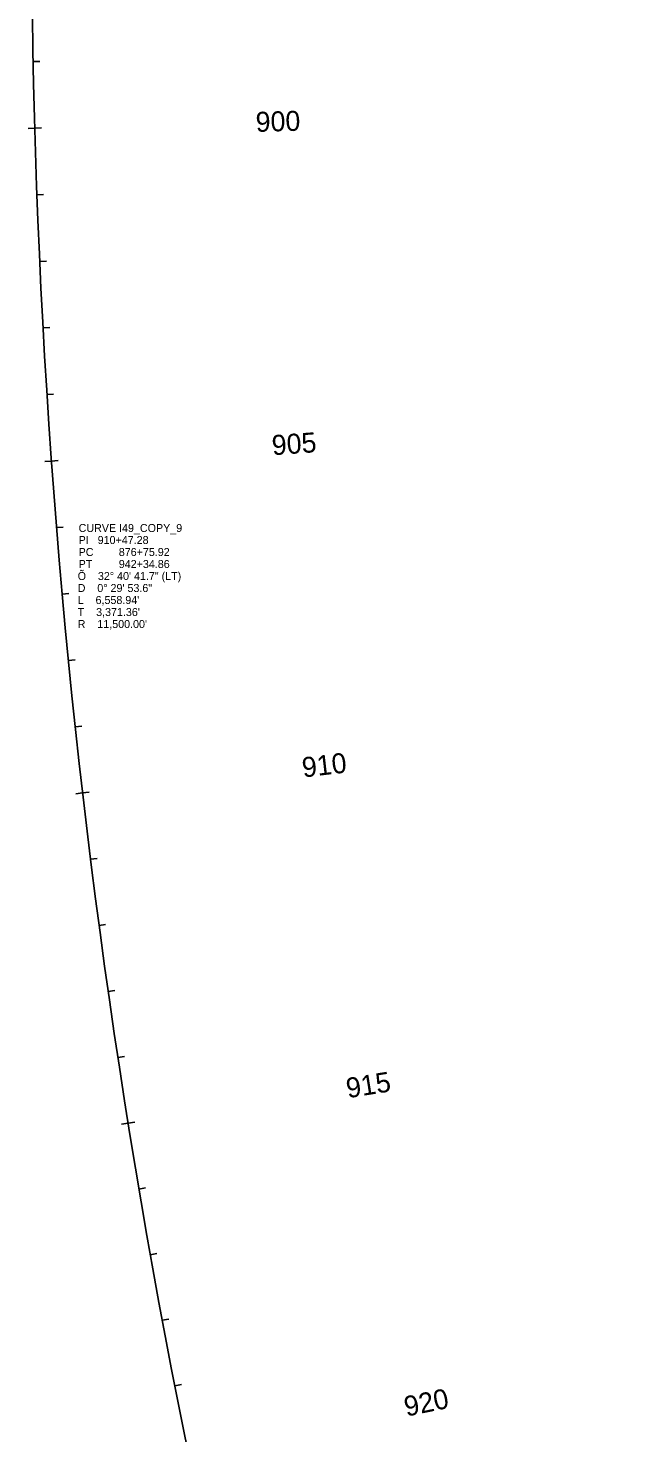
# Model space of a CAD drawing. Extents: x 2820825 to 2825694, y 116785 to 142398.
# Drawn here: x 2820828 to 2821726, y 127539 to 129646 of the extents above; entities that cross this region are included whole.
import ezdxf

# ---------------------------------------------------------------- set-up
doc = ezdxf.new("R2010")
doc.units = 0
for name, color, linetype in [('Default', 7, 'Continuous'), ('Roadway-Centerline main', 7, 'Continuous'), ('Text-Curve info', 7, 'Continuous')]:
    doc.layers.add(name, color=color, linetype=linetype)

msp = doc.modelspace()

# ---------------------------------------------------------------- linework, layer by layer
at = {"layer": 'Default'}
msp.add_arc((2832333.7, 129820.2), 11500, 170.03806, 202.7163, dxfattribs=at)
at = {"layer": 'Roadway-Centerline main'}
for p, q in [((2820835.9, 129595.7), (2820845.9, 129595.9)), ((2820838.3, 129495.7), (2820828.3, 129495.4)), ((2820838.3, 129495.7), (2820848.3, 129496)), ((2820841.5, 129395.8), (2820851.5, 129396.1)), ((2820845.7, 129295.8), (2820855.6, 129296.3)), ((2820850.7, 129196), (2820860.6, 129196.5)), ((2820856.5, 129096.1), (2820866.5, 129096.8)), ((2820863.2, 128996.4), (2820853.3, 128995.6)), ((2820863.2, 128996.4), (2820873.2, 128997.1)), ((2820870.8, 128896.6), (2820880.8, 128897.5)), ((2820879.3, 128797), (2820889.3, 128797.9)), ((2820888.6, 128697.4), (2820898.6, 128698.4)), ((2820898.8, 128598), (2820908.8, 128599)), ((2820909.9, 128498.6), (2820919.8, 128499.7)), ((2820909.9, 128498.6), (2820900, 128497.4)), ((2820921.8, 128399.3), (2820931.7, 128400.5)), ((2820934.6, 128300.1), (2820944.5, 128301.4)), ((2820948.3, 128201.1), (2820958.2, 128202.5)), ((2820962.8, 128102.1), (2820972.7, 128103.6)), ((2820978.1, 128003.3), (2820968.3, 128001.7)), ((2820978.1, 128003.3), (2820988, 128004.9)), ((2820994.4, 127904.6), (2821004.2, 127906.3)), ((2821011.4, 127806.1), (2821021.3, 127807.8)), ((2821029.4, 127707.7), (2821039.2, 127709.6)), ((2821048.2, 127609.5), (2821058, 127611.4))]:
    msp.add_line(p, q, dxfattribs=at)
msp.add_arc((2832333.7, 129820.2), 11500, 170.03806, 202.7163, dxfattribs=at)

# ---------------------------------------------------------------- texts
for s, rotation, p in [(' 900', 1.6172, (2821158.6, 129489.7)), (' 905', 4.1083, (2821183.5, 129004.3)), (' 910', 6.5994, (2821229.5, 128520.5)), (' 915', 9.0906, (2821296.5, 128039)), (' 920', 11.5817, (2821384.3, 127561))]:
    msp.add_text(s, height=30, rotation=rotation, dxfattribs=at).set_placement(p)
at = {"layer": 'Text-Curve info'}
for s, p in [('CURVE I49_COPY_9', (2820904, 128890)), ('PI   910+47.28', (2820904, 128872)), ('PC', (2820904, 128854)), ('876+75.92', (2820964.2, 128854)), ('PT', (2820904, 128836)), ('942+34.86', (2820964.2, 128836)), ('Õ    32%%d 40\' 41.7" (LT)', (2820902.6, 128818)), ('D    0%%d 29\' 53.6"', (2820902.6, 128800)), ("T    3,371.36'", (2820902.6, 128764)), ("L    6,558.94'", (2820902.6, 128782)), ("R    11,500.00'", (2820902.6, 128746))]:
    msp.add_text(s, height=12, dxfattribs=at).set_placement(p)

doc.saveas('drawing.dxf')
